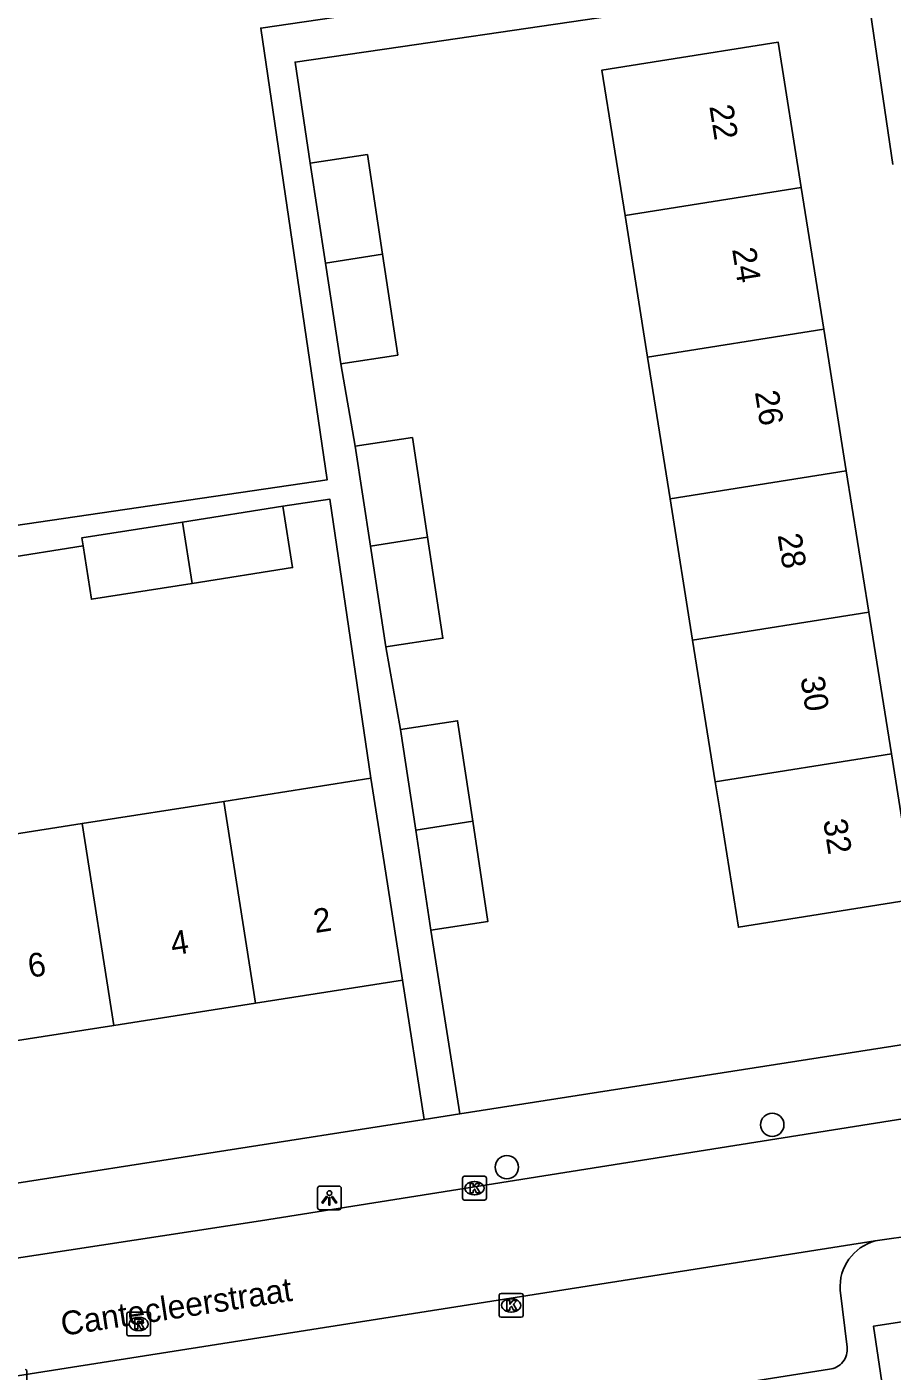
# Model space of a CAD drawing. Extents: x 160077 to 160945, y 386481 to 387498.
# Drawn here: x 160221.3 to 160257.7, y 387313.2 to 387369.8 of the extents above; entities that cross this region are included whole.
import ezdxf

# ---------------------------------------------------------------- set-up
doc = ezdxf.new("R2010")
doc.units = 0
for name, color, linetype in [('IMGEO_Boom', 7, 'Continuous'), ('IMGEO_Kolk', 7, 'Continuous'), ('IMGEO_Lichtpunt', 7, 'Continuous'), ('IMGEO_Openbare_ruimte_label', 7, 'Continuous'), ('IMGEO_Pand', 7, 'Continuous'), ('IMGEO_Pand_nummerreeks', 7, 'Continuous'), ('IMGEO_Rijbaan_lokaal_open', 7, 'Continuous'), ('IMGEO_Rioolput', 7, 'Continuous'), ('IMGEO_Voetpad_open', 7, 'Continuous')]:
    doc.layers.add(name, color=color, linetype=linetype)

msp = doc.modelspace()

# ---------------------------------------------------------------- linework, layer by layer
at = {"layer": 'IMGEO_Boom'}
for centre in [(160252.66, 387323.599), (160241.501, 387321.816)]:
    msp.add_circle(centre, 0.489, dxfattribs=at)
at = {"layer": 'IMGEO_Kolk'}
for p, q in [((160239.639, 387320.506), (160239.639, 387321.358)), ((160239.714, 387321.432), (160240.566, 387321.432)), ((160240.127, 387321.212), (160240.152, 387321.212)), ((160240.64, 387321.358), (160240.64, 387320.506)), ((160240.566, 387320.432), (160239.714, 387320.432)), ((160240.15, 387320.652), (160240.125, 387320.652)), ((160241.183, 387315.577), (160241.183, 387316.429)), ((160241.258, 387316.503), (160242.11, 387316.503)), ((160242.184, 387316.429), (160242.184, 387315.577)), ((160241.671, 387316.283), (160241.696, 387316.283)), ((160242.11, 387315.503), (160241.258, 387315.503)), ((160241.694, 387315.723), (160241.669, 387315.723)), ((160221.325, 387313.237), (160221.325, 387312.385))]:
    msp.add_line(p, q, dxfattribs=at)
for points in [[(160239.639, 387320.506), (160239.639, 387321.358)], [(160239.714, 387321.432), (160240.566, 387321.432)], [(160239.96, 387321.132), (160240.083, 387321.132), (160240.083, 387320.981), (160240.213, 387321.132), (160240.377, 387321.132), (160240.231, 387320.981), (160240.384, 387320.732), (160240.232, 387320.732), (160240.147, 387320.896), (160240.083, 387320.829), (160240.083, 387320.732), (160239.96, 387320.732), (160239.96, 387321.132)], [(160240.64, 387321.358), (160240.64, 387320.506)], [(160240.566, 387320.432), (160239.714, 387320.432)], [(160241.183, 387315.577), (160241.183, 387316.429)], [(160241.258, 387316.503), (160242.11, 387316.503)], [(160242.184, 387316.429), (160242.184, 387315.577)], [(160241.504, 387316.203), (160241.627, 387316.203), (160241.627, 387316.052), (160241.757, 387316.203), (160241.921, 387316.203), (160241.775, 387316.052), (160241.928, 387315.803), (160241.776, 387315.803), (160241.691, 387315.967), (160241.627, 387315.9), (160241.627, 387315.803), (160241.504, 387315.803), (160241.504, 387316.203)], [(160242.11, 387315.503), (160241.258, 387315.503)], [(160221.325, 387313.237), (160221.325, 387312.385)]]:
    msp.add_lwpolyline(points, dxfattribs=at)
for centre, start, end in [((160239.716, 387321.356), 91.552, 178.448), ((160239.716, 387321.356), 91.552, 178.448), ((160240.564, 387321.356), 1.552, 88.448), ((160240.564, 387321.356), 1.552, 88.448), ((160239.716, 387320.508), 181.552, 268.448), ((160239.716, 387320.508), 181.552, 268.448), ((160240.564, 387320.508), 271.552, 358.448), ((160240.564, 387320.508), 271.552, 358.448), ((160241.26, 387316.427), 91.552, 178.448), ((160241.26, 387316.427), 91.552, 178.448), ((160242.108, 387316.427), 1.552, 88.448), ((160242.108, 387316.427), 1.552, 88.448), ((160241.26, 387315.579), 181.552, 268.448), ((160241.26, 387315.579), 181.552, 268.448), ((160242.108, 387315.579), 271.552, 358.448), ((160242.108, 387315.579), 271.552, 358.448), ((160221.249, 387313.235), 1.552, 88.448), ((160221.249, 387313.235), 1.552, 88.448)]:
    msp.add_arc(centre, 0.0765, start, end, dxfattribs=at)
for centre, major_axis, ratio, start_param, end_param in [((160240.126, 387320.932), (-0.387, 0.002), 0.722429, 4.712389, 7.853982), ((160240.151, 387320.932), (-0.39, 0.002), 0.717154, 1.570796, 4.712389), ((160241.67, 387316.003), (-0.387, 0.002), 0.722429, 4.712389, 7.853982), ((160241.695, 387316.003), (-0.39, 0.002), 0.717154, 1.570796, 4.712389)]:
    msp.add_ellipse(centre, major_axis=major_axis, ratio=ratio, start_param=start_param, end_param=end_param, dxfattribs=at)
at = {"layer": 'IMGEO_Lichtpunt'}
for p, q in [((160233.543, 387320.926), (160233.543, 387320.119)), ((160233.543, 387320.926), (160233.543, 387320.119)), ((160234.445, 387321.021), (160233.637, 387321.021)), ((160234.445, 387321.021), (160233.637, 387321.021)), ((160234.539, 387320.119), (160234.539, 387320.926)), ((160234.539, 387320.119), (160234.539, 387320.926)), ((160233.637, 387320.025), (160234.445, 387320.025)), ((160233.637, 387320.025), (160234.445, 387320.025))]:
    msp.add_line(p, q, dxfattribs=at)
for points in [[(160233.917, 387320.59), (160233.956, 387320.562), (160233.768, 387320.3), (160233.73, 387320.327), (160233.917, 387320.59)], [(160234.019, 387320.542), (160234.066, 387320.542), (160234.066, 387320.22), (160234.019, 387320.22), (160234.019, 387320.542)], [(160234.129, 387320.562), (160234.167, 387320.589), (160234.354, 387320.327), (160234.315, 387320.299), (160234.129, 387320.562)]]:
    msp.add_lwpolyline(points, dxfattribs=at)
msp.add_circle((160234.042, 387320.724), 0.0994, dxfattribs=at)
for centre, start, end in [((160233.637, 387320.926), 90, 180), ((160233.637, 387320.926), 90, 180), ((160234.445, 387320.926), 0, 90), ((160234.445, 387320.926), 0, 90), ((160233.637, 387320.119), 180, 270), ((160233.637, 387320.119), 180, 270), ((160234.445, 387320.119), 270, 0), ((160234.445, 387320.119), 270, 360)]:
    msp.add_arc(centre, 0.0946, start, end, dxfattribs=at)
at = {"layer": 'IMGEO_Pand'}
for points in [[(160253.877, 387363.025), (160252.903, 387369.145), (160247.966, 387368.359), (160245.495, 387367.966), (160246.469, 387361.847)], [(160236.273, 387360.226), (160235.638, 387364.414), (160233.237, 387364.05)], [(160233.875, 387359.844), (160233.237, 387364.05)], [(160246.469, 387361.847), (160253.877, 387363.025)], [(160254.825, 387357.07), (160253.877, 387363.025)], [(160246.469, 387361.847), (160247.417, 387355.892)], [(160233.875, 387359.844), (160236.273, 387360.226)], [(160234.517, 387355.614), (160236.918, 387355.978), (160236.273, 387360.226)], [(160234.517, 387355.614), (160233.875, 387359.844)], [(160247.417, 387355.892), (160254.825, 387357.07)], [(160255.772, 387351.115), (160254.825, 387357.07)], [(160247.417, 387355.892), (160248.364, 387349.937)], [(160238.168, 387348.316), (160237.533, 387352.504), (160235.132, 387352.14)], [(160235.77, 387347.934), (160235.132, 387352.14)], [(160255.772, 387351.115), (160248.364, 387349.937)], [(160256.72, 387345.159), (160255.772, 387351.115)], [(160248.364, 387349.937), (160249.312, 387343.981)], [(160227.86, 387348.954), (160232.088, 387349.62)], [(160228.267, 387346.369), (160232.496, 387347.036), (160232.088, 387349.62)], [(160223.684, 387347.949), (160223.631, 387348.287), (160227.86, 387348.954)], [(160227.86, 387348.954), (160228.267, 387346.369)], [(160235.77, 387347.934), (160238.168, 387348.316)], [(160236.412, 387343.704), (160238.813, 387344.068), (160238.168, 387348.316)], [(160223.684, 387347.949), (160224.039, 387345.703), (160228.267, 387346.369)], [(160236.412, 387343.704), (160235.77, 387347.934)], [(160256.72, 387345.159), (160249.312, 387343.981)], [(160257.668, 387339.204), (160256.72, 387345.159)], [(160249.312, 387343.981), (160250.26, 387338.026)], [(160240.069, 387336.374), (160239.429, 387340.593), (160237.028, 387340.229)], [(160237.671, 387335.992), (160237.028, 387340.229)], [(160250.26, 387338.026), (160250.448, 387336.844), (160251.234, 387331.906), (160258.642, 387333.085), (160257.668, 387339.204)], [(160257.668, 387339.204), (160250.26, 387338.026)], [(160235.783, 387338.175), (160229.6, 387337.204)], [(160235.783, 387338.175), (160236.34, 387334.627), (160237.115, 387329.687)], [(160229.6, 387337.204), (160223.643, 387336.269)], [(160230.933, 387328.717), (160229.6, 387337.204)], [(160223.643, 387336.269), (160217.686, 387335.334)], [(160223.643, 387336.269), (160224.976, 387327.782)], [(160237.671, 387335.992), (160240.069, 387336.374)], [(160238.308, 387331.793), (160240.709, 387332.157), (160240.069, 387336.374)], [(160238.308, 387331.793), (160237.671, 387335.992)], [(160230.933, 387328.717), (160237.115, 387329.687)], [(160224.976, 387327.782), (160230.933, 387328.717)], [(160219.019, 387326.847), (160224.976, 387327.782)]]:
    msp.add_lwpolyline(points, dxfattribs=at)
at = {"layer": 'IMGEO_Rijbaan_lokaal_open'}
for points in [[(160261.761, 387324.424), (160231.152, 387319.558), (160178.484, 387311.5), (160179.39, 387306.487)], [(160256.989, 387318.714), (160262.324, 387319.479)], [(160179.39, 387306.487), (160196.527, 387309.19), (160256.989, 387318.714)]]:
    msp.add_lwpolyline(points, dxfattribs=at)
at = {"layer": 'IMGEO_Rioolput'}
for p, q in [((160225.525, 387314.793), (160225.525, 387315.645)), ((160225.6, 387315.719), (160226.452, 387315.719)), ((160226.013, 387315.499), (160226.038, 387315.499)), ((160226.526, 387315.645), (160226.526, 387314.793)), ((160226.452, 387314.719), (160225.6, 387314.719)), ((160226.036, 387314.939), (160226.011, 387314.939))]:
    msp.add_line(p, q, dxfattribs=at)
for points in [[(160225.525, 387314.793), (160225.525, 387315.645)], [(160225.6, 387315.719), (160226.452, 387315.719)], [(160226.114, 387315.417), (160225.862, 387315.419), (160225.862, 387315.019)], [(160226.04, 387315.338), (160225.986, 387315.338), (160225.986, 387315.257)], [(160225.986, 387315.257), (160226.038, 387315.257)], [(160226.526, 387315.645), (160226.526, 387314.793)], [(160226.452, 387314.719), (160225.6, 387314.719)], [(160225.862, 387315.019), (160225.986, 387315.019), (160225.986, 387315.181), (160225.997, 387315.181)], [(160226.044, 387315.152), (160226.115, 387315.019), (160226.255, 387315.019), (160226.19, 387315.145)]]:
    msp.add_lwpolyline(points, dxfattribs=at)
for centre, radius, start, end in [((160225.602, 387315.643), 0.0765, 91.552, 178.448), ((160225.602, 387315.643), 0.0765, 91.552, 178.448), ((160226.022, 387315.446), 0.19, 274.7715, 282.9687), ((160226.046, 387315.242), 0.0964, 77.0061, 93.1865), ((160226.06, 387315.299), 0.0378, 276.6634, 79.6772), ((160226.113, 387315.307), 0.109, 350.3612, 89.416), ((160226.111, 387315.307), 0.112, 277.5842, 350.9817), ((160226.45, 387315.643), 0.0765, 1.552, 88.448), ((160226.45, 387315.643), 0.0765, 1.552, 88.448), ((160225.602, 387314.795), 0.0765, 181.552, 268.448), ((160225.602, 387314.795), 0.0765, 181.552, 268.448), ((160225.996, 387315.128), 0.0533, 26.0293, 88.6989), ((160226.095, 387315.092), 0.108, 29.5134, 73.7905), ((160226.45, 387314.795), 0.0765, 271.552, 358.448), ((160226.45, 387314.795), 0.0765, 271.552, 358.448)]:
    msp.add_arc(centre, radius, start, end, dxfattribs=at)
for centre, major_axis, ratio, start_param, end_param in [((160226.012, 387315.219), (-0.387, 0.002), 0.722429, 4.712389, 7.853982), ((160226.037, 387315.219), (-0.39, 0.002), 0.717154, 1.570796, 4.712389)]:
    msp.add_ellipse(centre, major_axis=major_axis, ratio=ratio, start_param=start_param, end_param=end_param, dxfattribs=at)
at = {"layer": 'IMGEO_Voetpad_open'}
for points in [[(160173.24, 387325.04), (160170.577, 387341.434), (160233.943, 387350.726), (160231.156, 387369.73), (160256.864, 387373.5), (160253.922, 387391.053), (160257.501, 387391.612)], [(160233.237, 387364.05), (160232.602, 387368.301), (160237.025, 387368.95), (160256.577, 387371.817), (160257.725, 387363.991)], [(160235.132, 387352.14), (160234.517, 387355.614)], [(160232.088, 387349.62), (160234.062, 387349.91), (160235.783, 387338.175)], [(160220.163, 387347.393), (160223.684, 387347.949)], [(160237.028, 387340.229), (160236.412, 387343.704)], [(160239.518, 387324.06), (160238.308, 387331.793)], [(160237.115, 387329.687), (160238.032, 387323.828)], [(160260.423, 387327.331), (160239.518, 387324.06)], [(160238.032, 387323.828), (160176.51, 387314.203)], [(160238.032, 387323.828), (160239.518, 387324.06)], [(160255.516, 387316.647), (160255.802, 387314.249)], [(160249.267, 387311.299), (160257.302, 387312.495), (160256.918, 387315.132), (160262.495, 387315.99)], [(160255.062, 387313.319), (160183.569, 387302.016)]]:
    msp.add_lwpolyline(points, dxfattribs=at)
for centre, radius, start, end in [((160257.509, 387316.785), 1.998, 105.0872, 183.9634), ((160254.988, 387314.137), 0.822, 275.1622, 7.8193)]:
    msp.add_arc(centre, radius, start, end, dxfattribs=at)

# ---------------------------------------------------------------- texts
at = {"layer": 'IMGEO_Openbare_ruimte_label'}
msp.add_text('Cantecleerstraat', height=1, rotation=8.6895, dxfattribs=at).set_placement((160222.83, 387314.717))
at = {"layer": 'IMGEO_Pand_nummerreeks'}
for s, rotation, p in [('22', 279.0429, (160250.012, 387366.444)), ('24', 279.0429, (160250.969, 387360.431)), ('26', 279.0429, (160251.925, 387354.421)), ('28', 279.0429, (160252.883, 387348.408)), ('30', 279.0429, (160253.839, 387342.398)), ('32', 279.0429, (160254.795, 387336.394)), ('2', 8.9208, (160233.448, 387331.662)), ('4', 8.9208, (160227.448, 387330.721)), ('6', 8.9208, (160221.447, 387329.779))]:
    msp.add_text(s, height=1, rotation=rotation, dxfattribs=at).set_placement(p)

doc.saveas('drawing.dxf')
